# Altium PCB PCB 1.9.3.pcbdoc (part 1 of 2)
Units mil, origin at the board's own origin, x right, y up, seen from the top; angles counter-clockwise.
Board outline 4192.9 x 2374.1 mil, 2 copper layers (Top Layer, Bottom Layer), stack 62.2 mil thick; 67 components, 68 nets, 279 pads, 489 vias.
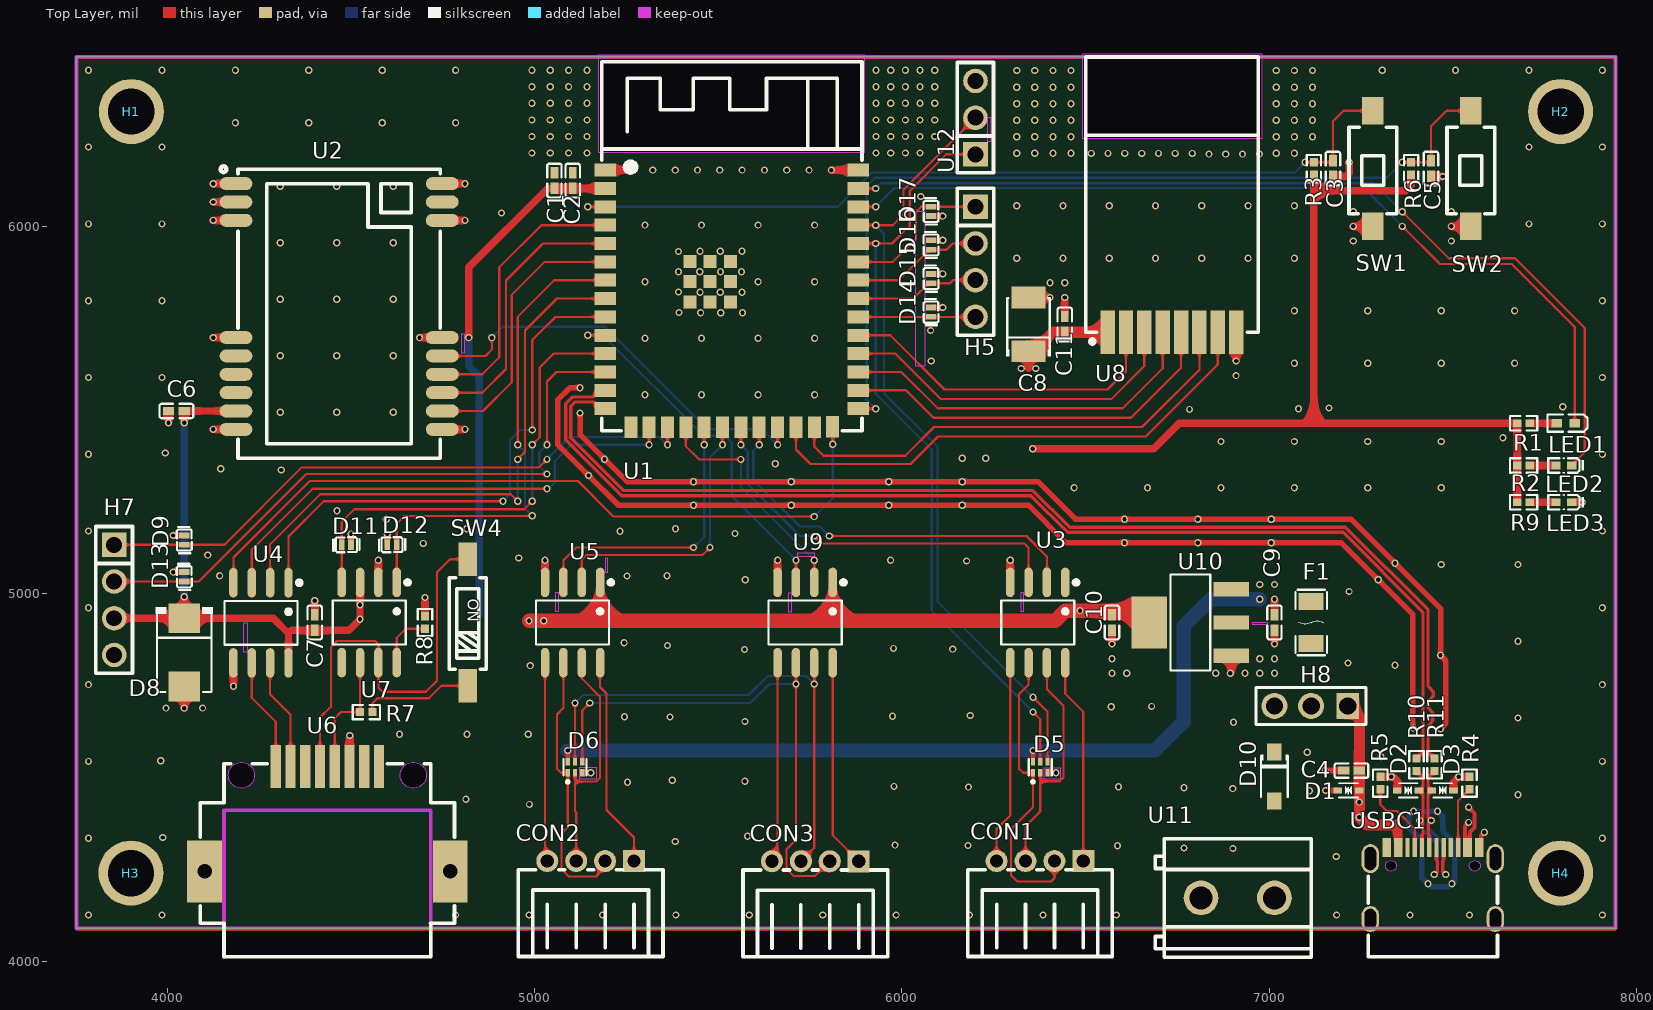
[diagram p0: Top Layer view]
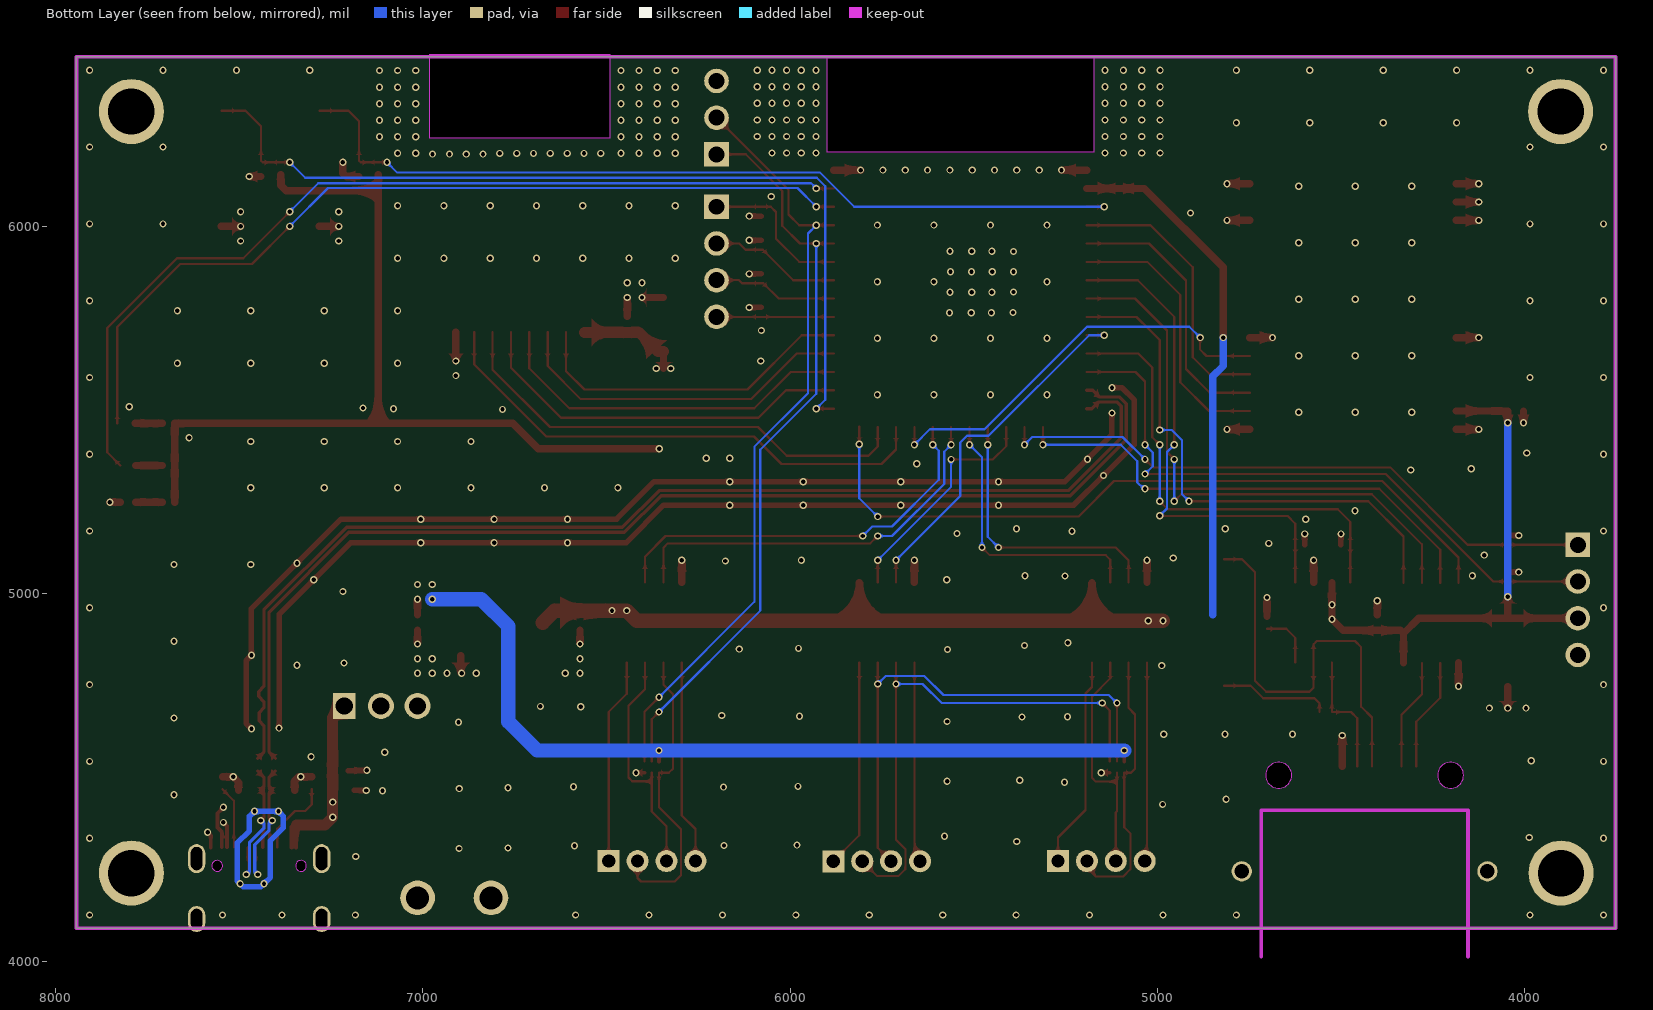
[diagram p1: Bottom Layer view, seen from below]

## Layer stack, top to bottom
Top Solder Mask Layer: solder mask 0.4, Dk 3.3
Top Layer: signal copper 1.4
Dielectric1: surface 59.4, FR4, Dk 4.5
Bottom Layer: signal copper 1.4
Bottom Solder Mask Layer: solder mask 0.4, Dk 3.3

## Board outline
3751.1,6463.8 3751.1,4089.7 7944,4089.7 7944,6463.8
cut-out: 5172.3,6466.8 5172.3,6203.7 5899.1,6203.7 5899.1,6466.8
cut-out: 6491.1,6469.7 6491.1,6240.7 6981.1,6240.7 6981.1,6469.7

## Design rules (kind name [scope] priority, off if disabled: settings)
BoardOutlineClearance copperThickness1oz [All] p0: genericclearance=10 ignorepadtopadclearanceinfootprint=FALSE except(0: Arc-SplitContinuation Track-SplitContinuation SMDPad-SplitContinuation THPad-SplitContinuation Via-SplitContinuation Fill-SplitContinuation Poly-SplitContinuation Region-SplitContinuation Text-SplitContinuation)
BoardOutlineClearance Plane_innerPlane [All] p0: genericclearance=10 ignorepadtopadclearanceinfootprint=FALSE except(0: Arc-SplitContinuation Track-SplitContinuation SMDPad-SplitContinuation THPad-SplitContinuation Via-SplitContinuation Fill-SplitContinuation Poly-SplitContinuation Region-SplitContinuation Text-SplitContinuation)
BoardOutlineClearance Copper_copperRegion [All] p0: genericclearance=10 ignorepadtopadclearanceinfootprint=FALSE except(0: Arc-SplitContinuation Track-SplitContinuation SMDPad-SplitContinuation THPad-SplitContinuation Via-SplitContinuation Fill-SplitContinuation Poly-SplitContinuation Region-SplitContinuation Text-SplitContinuation)
BoardOutlineClearance Copper_CX [All] p0: genericclearance=10 ignorepadtopadclearanceinfootprint=FALSE except(0: Arc-SplitContinuation Track-SplitContinuation SMDPad-SplitContinuation THPad-SplitContinuation Via-SplitContinuation Fill-SplitContinuation Poly-SplitContinuation Region-SplitContinuation Text-SplitContinuation)
BoardOutlineClearance otherClearance [All] p0: genericclearance=10 ignorepadtopadclearanceinfootprint=FALSE except(0: Arc-SplitContinuation Track-SplitContinuation SMDPad-SplitContinuation THPad-SplitContinuation Via-SplitContinuation Fill-SplitContinuation Poly-SplitContinuation Region-SplitContinuation Text-SplitContinuation)
Clearance copperThickness1oz [All] p1: gap=7 ignorepadtopadclearanceinfootprint=FALSE
Clearance Plane_innerPlane [All] p1: gap=7 ignorepadtopadclearanceinfootprint=FALSE
Clearance Copper_copperRegion [All] p1: gap=7 ignorepadtopadclearanceinfootprint=FALSE
Clearance Copper_CX [All] p1: gap=7 ignorepadtopadclearanceinfootprint=FALSE
Clearance otherClearance [All] p1: gap=7 ignorepadtopadclearanceinfootprint=FALSE
DiffPairsRouting differentialPair [All] p1: maxuncoupledlength=10 minlimit=5 maxlimit=Infinity mostfreqgap=5 toplayer_minwidth=9 toplayer_prefwidth=9 toplayer_maxwidth=9 bottomlayer_minwidth=9 bottomlayer_prefwidth=9 bottomlayer_maxwidth=9
PasteMaskExpansion pasteMaskExpansion [All] p1: expansion=0
PlaneConnect innerPlane [All] p1: planeconnectstyle=Relief reliefexpansion=20 reliefentries=4 reliefconductorwidth=10 reliefairgap=10
PolygonConnect copperRegion [All] p1: connectstyle=Direct reliefentries=4 reliefconductorwidth=10 polygonreliefangle="90 Angle" airgapwidth=10
PolygonConnect CX [All] p1: connectstyle=Direct reliefentries=4 reliefconductorwidth=10 polygonreliefangle="90 Angle" airgapwidth=10
RoutingVias viaSize [All] p1: viastyle="Through Hole" holewidth=11.8 minholewidth=11.8 maxholewidth=11.8 width=11.8 minwidth=11.8 maxwidth=11.8
SolderMaskExpansion solderMaskExpansion [IsVia] p1: useseparateexpansions=TRUE expansion=-1000 expansionbottom=-1000
SolderMaskExpansion solderMaskExpansion [All] p2: useseparateexpansions=TRUE expansion=2 expansionbottom=2
Width copperThickness1oz [All] p1: maxlimit=100 minlimit=5 preferedwidth=6

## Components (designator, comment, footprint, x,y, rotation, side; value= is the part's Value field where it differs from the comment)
C1 "22uF" C0402_4#1 5053.2,6126.1 r270 top
C2 "100nF" C0402_4#1 5103.2,6126.1 r270 top
C3 "100nF" C0402_4#1 7174.1,6158.8 r90 top
C4 "100nF" C0402_4#1 7224.5,4518.7 r0 top
C5 "100nF" C0402_4#1 7441.1,6158.8 r90 top
C6 "100nF" C0402_4#1 4023.4,5498.3 r0 top
C7 "100nF" C0402_4#2 4400.1,4922.1 r270 top
C8 "100uF" CASE-B_3531 6344.7,5734.2 r90 top
C9 "10uF" C0402_4#2 7014.7,4922.1 r270 top
C10 "10uF" C0402_4#3 6572.1,4922.1 r90 top
C11 "100nF" C0402_4#3 6443.3,5734.2 r90 top
CON1 "PH-4AW_C722777" CONN-TH_PH-4AW_C722777_3 6376,4272.2 r0 top
CON2 "PH-4AW_C722777" CONN-TH_PH-4AW_C722777_3 5152,4272.2 r0 top
CON3 "PH-4AW_C722777" CONN-TH_PH-4AW_C722777_3 5764,4271.7 r0 top
D1 "LESD5D5.0CT1G" SOD-523_L1.2-W0.8-LS1.6-BI_4#1 7216.4,4464.7 r0 top
D2 "LESD5D5.0CT1G" SOD-523_L1.2-W0.8-LS1.6-BI_4#2 7379.2,4464.7 r0 top
D3 "LESD5D5.0CT1G" SOD-523_L1.2-W0.8-LS1.6-BI_4#1 7473.2,4464.7 r180 top
D5 "TPD4E004DRYR" SON-6_L1.5-W1.0-P0.50-BL_4#1 6376.7,4528 r0 top
D6 "TPD4E004DRYR" SON-6_L1.5-W1.0-P0.50-BL_4#2 5109.4,4528 r0 top
D8 "SMLVT3V3" SMB_L4.6-W3.6-LS5.3-RD_3 4044.9,4840.9 r270 top
D9 "DESD3V3E1BL-7B" X1-DFN1006-2_L1.0-W0.6-P0.65-BI_2 4044.9,5146.6 r270 top
D10 "LMBR220FT1G" SOD-123F_L2.7-W1.7-LS3.7-RD-1_5 7014.7,4502.7 r270 top
D11 "DESD3V3E1BL-7B" X1-DFN1006-2_L1.0-W0.6-P0.65-BI_2 4486.5,5133.8 r0 top
D12 "DESD3V3E1BL-7B" X1-DFN1006-2_L1.0-W0.6-P0.65-BI_2 4610.9,5133.8 r180 top
D13 "DESD3V3E1BL-7B" X1-DFN1006-2_L1.0-W0.6-P0.65-BI_2 4044.9,5046.6 r270 top
D14 "DESD3V3E1BL-7B" X1-DFN1006-2_L1.0-W0.6-P0.65-BI_2 6079.1,5767.6 r270 top
D15 "DESD3V3E1BL-7B" X1-DFN1006-2_L1.0-W0.6-P0.65-BI_2 6079.1,5859.1 r270 top
D16 "DESD3V3E1BL-7B" X1-DFN1006-2_L1.0-W0.6-P0.65-BI_2 6079.1,5950.6 r270 top
D17 "DESD3V3E1BL-7B" X1-DFN1006-2_L1.0-W0.6-P0.65-BI_2 6079.1,6042 r90 top
F1 "Resettable Fuse" F1206_3 7114.7,4922.1 r90 top
H1 "PZ254V-11-01P" HDR-TH_1P-P2.54-V-M_2 3900.7,6314.2 r0 top
H2 "PZ254V-11-01P" HDR-TH_1P-P2.54-V-M_2 7794.4,6314.2 r0 top
H3 "PZ254V-11-01P" HDR-TH_1P-P2.54-V-M_2 3899.7,4239.4 r0 top
H4 "PZ254V-11-01P" HDR-TH_1P-P2.54-V-M_2 7794.4,4239.4 r0 top
H5 "Header-Male-2.54_1x4" HDR-TH_4P-P2.54-V-M_3 6200.3,5904.8 r270 top
H7 "Header-Male-2.54_1x4" HDR-TH_4P-P2.54-V-M_3 3853.9,4983.8 r270 top
H8 "Header-Male-2.54_1x3" HDR-TH_3P-P2.54-V-M-1_3 7114.7,4694.9 r180 top
LED1 "BLUE" LED0402-R-RD_3 7808.2,5464.9 r180 top
LED2 "GREEN" LED0402-RD_GREEN_3 7803.2,5349.9 r180 top
LED3 "White" LED0402-RD_WHITE_3 7803.2,5249.9 r180 top
R1 "1.5kΩ" R0402_3#1 7693.2,5464.9 r0 top
R2 "1.5kΩ" R0402_3#1 7693.2,5349.9 r0 top
R3 "10kΩ" R0402_3#2 7122.1,6158.8 r270 top
R4 "5.1kΩ" R0402_3#3 7546.2,4484.7 r270 top
R5 "5.1kΩ" R0402_3#3 7303.2,4484.7 r270 top
R6 "10kΩ" R0402_3#2 7387.1,6158.8 r270 top
R7 "120Ω" R0402_3#2 4540.8,4678.2 r180 top
R8 "10kΩ" R0402_3#3 4700.8,4922.1 r270 top
R9 "1.5kΩ" R0402_3#3 7693.2,5249.9 r180 top
R10 "22Ω" R0402_3#1 7401.7,4534.7 r90 top
R11 "22Ω" R0402_3#1 7450.6,4534.7 r90 top
SW1 "TS-1101-C-W" SW-SMD_L6.0-W3.3-LS8.0_3 7282.1,6158.8 r90 top
SW2 "TS-1101-C-W" SW-SMD_L6.0-W3.3-LS8.0_3 7549.1,6158.8 r90 top
SW4 "DSIC01LSGET" SW-SMD_DSIC01LSGET_3 4817.1,4922.1 r0 top
U1 "ESP32-S3-WROOM-1-N16R8" WIRELM-SMD_ESP32-S3-WROOM-1_4 5536.2,5804.4 r0 top
U2 "E49-900M20S" WIRELM-SMD_E49-400M20S_3 4466.8,5783 r180 top
U3 "ADUM1201AR-RL7" SOIC-8_L4.9-W3.9-P1.27-LS6.0-BL_3 6369.8,4922.1 r180 top
U4 "ISL3178EIBZ-T" SOIC-8_L4.9-W3.9-P1.27-LS6.0-BL_3 4253.8,4921.2 r180 top
U5 "ADUM1201AR-RL7" SOIC-8_L4.9-W3.9-P1.27-LS6.0-BL_3 5102.6,4922.1 r180 top
U6 "HC-RJ45-055-4" RJ45-SMD_HC-RJ45-055-4_5 4434.7,4387 r0 top
U7 "SN65HVD230DR" SOIC-8_L4.9-W3.9-P1.27-LS6.0-BL_3 4548.7,4922.1 r180 top
U8 "E01-ML01S" WIRELM-SMD_E01-ML01S_3 6735.3,5712.8 r0 top
U9 "ADUM1201AR-RL7" SOIC-8_L4.9-W3.9-P1.27-LS6.0-BL_3 5736.2,4922.1 r180 top
U10 "AMS1117-3.3" SOT-223-4_L6.5-W3.5-P2.30-LS7.0-BR_3 6785.6,4922.1 r0 top
U11 "KF127-5.08-2P" CONN-TH_P5.08_KF127-5.08-2P_3 6914.7,4172 r0 top
U12 "HB-PH3-25413PB2GOP" HDR-TH_3P-P2.54-V-M_3 6200.3,6297.5 r90 top
USBC1 "TYPE-C-31-M-12" USB-C_SMD-TYPE-C-31-M-12_3 7446.2,4211.8 r0 top

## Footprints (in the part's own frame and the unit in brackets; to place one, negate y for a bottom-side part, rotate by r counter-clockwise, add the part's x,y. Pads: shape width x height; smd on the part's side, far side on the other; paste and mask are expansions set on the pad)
C0402_4#1 [mil]
  rect 31.1x21.3 smd paste-3937 mask+2: 1(-21.5,0) 2(21.5,0)
  silkscreen extent -46,-20 46,20
C0402_4#2 [mil]
  rect 31.1x21.3 smd paste-3937 mask+2: 1(-21.5,0) 2(21.4,0)
  silkscreen extent -46,-20 46,20
C0402_4#3 [mil]
  rect 31.1x21.3 smd paste-3937 mask+2: 1(-21.4,0) 2(21.5,0)
  silkscreen extent -46,-20 46,20
CASE-B_3531 [mil]
  rect 59.3x93.5 smd: 1(-73.2,0) 2(73.3,0)
  silkscreen extent -87,-61 72,61
CONN-TH_P5.08_KF127-5.08-2P_3 [mil]
  round 94.5 hole 63: 1(-100,0) 2(100,0)
  silkscreen extent -225,-161 200,161
CONN-TH_PH-4AW_C722777_3 [mil]
  rect 60x60 hole 36: 1(118.1,0)
  round 60 hole 36: 2(39.3,0) 3(-39.4,0) 4(-118.2,0)
  silkscreen extent -197,-260 197,-24
F1206_3 [mil]
  rect 46.9x68 smd: 1(-56.8,0) 2(56.9,0)
  silkscreen extent -89,-43 89,43
HDR-TH_1P-P2.54-V-M_2 [mil]
  round 177.2 hole 126: 1(0,0)
HDR-TH_3P-P2.54-V-M-1_3 [mil]
  rect 62x70.9 hole 47.2: 1(-100,0)
  round 70.9 hole 47.2: 2(0,0) 3(100,0)
  silkscreen extent -150,-50 150,50
HDR-TH_3P-P2.54-V-M_3 [mil]
  rect 66.9x66.9 hole 43.3: 1(-100,0)
  round 66.9 hole 43.3: 2(0,0) 3(100,0)
  silkscreen extent -150,-49 150,49
HDR-TH_4P-P2.54-V-M_3 [mil]
  rect 66.9x66.9 hole 43.3: 1(-150,0)
  round 66.9 hole 43.3: 2(-50,0) 3(50,0) 4(150,0)
  silkscreen extent -200,-50 200,50
LED0402-R-RD_3 [mil]
  rect 29.5x23.6 smd: 1(24.5,0) 2(-24.5,0)
  silkscreen extent -60,-24 50,23
LED0402-RD_GREEN_3 [mil]
  rect 25.1x21.3 smd paste-3937 mask+2: 1(-21.2,0) 2(21.2,0)
  silkscreen extent -55,-21 43,21
LED0402-RD_WHITE_3 [mil]
  rect 25.1x21.3 smd paste-3937 mask+2: 1(-21.2,0) 2(21.2,0)
  silkscreen extent -55,-21 43,21
R0402_3#1 [mil]
  rect 22.3x21.3 smd paste-3937 mask+2: 1(-17,0) 2(17.1,0)
  silkscreen extent -37,-20 37,20
R0402_3#2 [mil]
  rect 22.3x21.3 smd paste-3937 mask+2: 1(-17,0) 2(17,0)
  silkscreen extent -37,-20 37,20
R0402_3#3 [mil]
  rect 22.3x21.3 smd paste-3937 mask+2: 1(-17.1,0) 2(17,0)
  silkscreen extent -37,-20 37,20
RJ45-SMD_HC-RJ45-055-4_5 [mil]
  rect 27.6x118.1 smd paste-3937 mask+2: 1(-140.5,142.7) 2(-100.4,142.7) 3(-60.2,142.7) 4(-20.1,142.7) 5(20.1,142.7) 6(60.2,142.7) 7(100.4,142.7) 8(140.6,142.7)
  rect 94.5x169.3 smd paste-3937 mask+2: 9(-334.6,-142.7) 10(334.7,-142.7)
  round 55.1 hole 39.4 paste+0 mask+2: 9(-334.6,-142.7) 10(334.7,-142.7)
  Board Outline Layer lines w0.1: -269.7,119.1 -269.3,113.8 -268.1,108.6 -266.2,103.7 -263.5,99.1 -260.2,95 -256.3,91.4 -252,88.4 -247.2,86.1 -242.1,84.5 -236.9,83.8 -231.6,83.8 -226.4,84.5 -221.3,86.1 -216.5,88.4 -212.1,91.4 -208.3,95 -205,99.1 -202.3,103.7 -200.4,108.6 -199.2,113.8 -198.8,119.1 -199.2,124.4 -200.4,129.5 -202.3,134.5 -205,139 -208.3,143.2 -212.1,146.8 -216.5,149.8 -221.3,152.1 -226.4,153.6 -231.6,154.4 -236.9,154.4 -242.1,153.6 -247.2,152.1 -252,149.8 -256.3,146.8 -260.2,143.2 -263.5,139 -266.2,134.5 -268.1,129.5 -269.3,124.4 -269.7,119.1 ; 198.8,119.1 199.2,113.8 200.4,108.6 202.3,103.7 205,99.1 208.3,95 212.2,91.4 216.5,88.4 221.3,86.1 226.4,84.5 231.6,83.8 236.9,83.8 242.1,84.5 247.2,86.1 252,88.4 256.4,91.4 260.2,95 263.5,99.1 266.2,103.7 268.1,108.6 269.3,113.8 269.7,119.1 269.3,124.4 268.1,129.5 266.2,134.5 263.5,139 260.2,143.2 256.4,146.8 252,149.8 247.2,152.1 242.1,153.6 236.9,154.4 231.6,154.4 226.4,153.6 221.3,152.1 216.5,149.8 212.2,146.8 208.3,143.2 205,139 202.3,134.5 200.4,129.5 199.2,124.4 198.8,119.1
  Board Outline Layer lines w10: -281.5,-375 -281.5,23.6 281.5,23.6 ; 281.5,-375 281.5,23.6 ; 281.5,23.6 281.5,23.6
  Board Outline Layer region: -198.8,119.1 -199.2,113.8 -200.4,108.6 -202.3,103.7 -205,99.1 -208.3,95 -212.1,91.4 -216.5,88.4 -221.3,86.1 -226.4,84.5 -231.6,83.8 -236.9,83.8 -242.1,84.5 -247.2,86.1 -252,88.4 -256.3,91.4 -260.2,95 -263.5,99.1 -266.2,103.7 -268.1,108.6 -269.3,113.8 -269.7,119.1 -269.3,124.4 -268.1,129.5 -266.2,134.5 -263.5,139 -260.2,143.2 -256.3,146.8 -252,149.8 -247.2,152.1 -242.1,153.6 -236.9,154.4 -231.6,154.4 -226.4,153.6 -221.3,152.1 -216.5,149.8 -212.1,146.8 -208.3,143.2 -205,139 -202.3,134.5 -200.4,129.5 -199.2,124.4
  Board Outline Layer region: -198.8,119.1 -199.2,113.8 -200.4,108.6 -202.3,103.7 -205,99.1 -208.3,95 -212.1,91.4 -216.5,88.4 -221.3,86.1 -226.4,84.5 -231.6,83.8 -236.9,83.8 -242.1,84.5 -247.2,86.1 -252,88.4 -256.3,91.4 -260.2,95 -263.5,99.1 -266.2,103.7 -268.1,108.6 -269.3,113.8 -269.7,119.1 -269.3,124.4 -268.1,129.5 -266.2,134.5 -263.5,139 -260.2,143.2 -256.3,146.8 -252,149.8 -247.2,152.1 -242.1,153.6 -236.9,154.4 -231.6,154.4 -226.4,153.6 -221.3,152.1 -216.5,149.8 -212.1,146.8 -208.3,143.2 -205,139 -202.3,134.5 -200.4,129.5 -199.2,124.4
  Board Outline Layer region: 269.7,119.1 269.3,113.8 268.1,108.6 266.2,103.7 263.5,99.1 260.2,95 256.4,91.4 252,88.4 247.2,86.1 242.1,84.5 236.9,83.8 231.6,83.8 226.4,84.5 221.3,86.1 216.5,88.4 212.2,91.4 208.3,95 205,99.1 202.3,103.7 200.4,108.6 199.2,113.8 198.8,119.1 199.2,124.4 200.4,129.5 202.3,134.5 205,139 208.3,143.2 212.2,146.8 216.5,149.8 221.3,152.1 226.4,153.6 231.6,154.4 236.9,154.4 242.1,153.6 247.2,152.1 252,149.8 256.4,146.8 260.2,143.2 263.5,139 266.2,134.5 268.1,129.5 269.3,124.4
  Board Outline Layer region: 269.7,119.1 269.3,113.8 268.1,108.6 266.2,103.7 263.5,99.1 260.2,95 256.4,91.4 252,88.4 247.2,86.1 242.1,84.5 236.9,83.8 231.6,83.8 226.4,84.5 221.3,86.1 216.5,88.4 212.2,91.4 208.3,95 205,99.1 202.3,103.7 200.4,108.6 199.2,113.8 198.8,119.1 199.2,124.4 200.4,129.5 202.3,134.5 205,139 208.3,143.2 212.2,146.8 216.5,149.8 221.3,152.1 226.4,153.6 231.6,154.4 236.9,154.4 242.1,153.6 247.2,152.1 252,149.8 256.4,146.8 260.2,143.2 263.5,139 266.2,134.5 268.1,129.5 269.3,124.4
  Multi-Layer board cut-out: -198.8,119.1 -199.2,113.8 -200.4,108.6 -202.3,103.7 -205,99.1 -208.3,95 -212.1,91.4 -216.5,88.4 -221.3,86.1 -226.4,84.5 -231.6,83.8 -236.9,83.8 -242.1,84.5 -247.2,86.1 -252,88.4 -256.3,91.4 -260.2,95 -263.5,99.1 -266.2,103.7 -268.1,108.6 -269.3,113.8 -269.7,119.1 -269.3,124.4 -268.1,129.5 -266.2,134.5 -263.5,139 -260.2,143.2 -256.3,146.8 -252,149.8 -247.2,152.1 -242.1,153.6 -236.9,154.4 -231.6,154.4 -226.4,153.6 -221.3,152.1 -216.5,149.8 -212.1,146.8 -208.3,143.2 -205,139 -202.3,134.5 -200.4,129.5 -199.2,124.4
  Multi-Layer board cut-out: 269.7,119.1 269.3,113.8 268.1,108.6 266.2,103.7 263.5,99.1 260.2,95 256.4,91.4 252,88.4 247.2,86.1 242.1,84.5 236.9,83.8 231.6,83.8 226.4,84.5 221.3,86.1 216.5,88.4 212.2,91.4 208.3,95 205,99.1 202.3,103.7 200.4,108.6 199.2,113.8 198.8,119.1 199.2,124.4 200.4,129.5 202.3,134.5 205,139 208.3,143.2 212.2,146.8 216.5,149.8 221.3,152.1 226.4,153.6 231.6,154.4 236.9,154.4 242.1,153.6 247.2,152.1 252,149.8 256.4,146.8 260.2,143.2 263.5,139 266.2,134.5 268.1,129.5 269.3,124.4
  silkscreen extent -346,-375 346,151
SMB_L4.6-W3.6-LS5.3-RD_3 [mil]
  rect 80.6x86.3 smd: 1(-92.9,0) 2(93,0)
  silkscreen extent -123,-77 108,77
SOD-123F_L2.7-W1.7-LS3.7-RD-1_5 [mil]
  rect 47.2x39.4 smd: 1(-66.9,0) 2(67,0)
  silkscreen extent -59,-37 56,37
SOD-523_L1.2-W0.8-LS1.6-BI_4#1 [mil]
  rect 23.6x15.7 smd: 1(-29.5,0) 2(29.6,0)
  silkscreen extent -26,-20 26,20
SOD-523_L1.2-W0.8-LS1.6-BI_4#2 [mil]
  rect 23.6x15.7 smd: 1(-29.6,0) 2(29.5,0)
  silkscreen extent -26,-20 26,20
SOIC-8_L4.9-W3.9-P1.27-LS6.0-BL_3 [mil]
  oval 23.1x80.5 smd: 1(-75,-109.2) 2(-25,-109.2) 3(25,-109.2) 4(75,-109.2) 5(75,109.1) 6(25,109.1) 7(-25,109.1) 8(-75,109.1)
  silkscreen extent -110,-115 99,60
SON-6_L1.5-W1.0-P0.50-BL_4#1 [mil]
  rect 11.8x20.5 smd: 1(-19.7,-15.1) 2(0,-15.1) 3(19.7,-15.1) 4(19.7,15.2) 5(0,15.2) 6(-19.7,15.2)
  silkscreen extent -32,-44 32,23
SON-6_L1.5-W1.0-P0.50-BL_4#2 [mil]
  rect 11.8x20.5 smd: 1(-19.6,-15.1) 2(0,-15.1) 3(19.7,-15.1) 4(19.7,15.2) 5(0,15.2) 6(-19.6,15.2)
  silkscreen extent -32,-44 32,23
SOT-223-4_L6.5-W3.5-P2.30-LS7.0-BR_3 [mil]
  rect 97.2x38.6 smd: 1(111.6,-90.5) 2(111.6,0) 3(111.6,90.6)
  rect 97.2x141.7 smd: 4(-111.6,0)
  silkscreen extent -54,-131 54,131
SW-SMD_DSIC01LSGET_3 [mil]
  rect 51.2x90.6 smd: 1(0,172.3) 2(0,-172.2)
  silkscreen extent -50,-128 50,122
SW-SMD_L6.0-W3.3-LS8.0_3 [mil]
  rect 74.8x59.1 smd: 1(-157.5,0) 2(157.5,0)
  silkscreen extent -124,-66 113,64
USB-C_SMD-TYPE-C-31-M-12_3 [mil]
  oval 47.2x78.7 hole 31.5 slot 63 at 90 deg: 0(-170.3,67.2) 1(170.3,67.2)
  oval 47.2x70.9 hole 31.5 slot 55.1 at 90 deg: 2(170.3,-97.4) 3(-170.3,-97.4)
  rect 11.8x51.2 smd paste-3937 mask+2: A1(-131.9,97.4) A4(-100.4,97.4) A5(-49.2,97.4) A6(-9.9,97.4) A7(9.8,97.4) A8(49.2,97.4) A9(100.4,97.4) A12(131.9,97.4) B1(120.1,97.4) B4(88.6,97.4) B5(68.9,97.4) B6(29.5,97.4) B7(-29.6,97.4) B8(-68.9,97.4) B9(-88.6,97.4) B12(-120.1,97.4)
  Board Outline Layer lines w0.1: -128.9,45.8 -128.1,42.5 -126.5,39.4 -124.3,36.8 -121.6,34.7 -118.4,33.4 -115.1,32.8 -111.6,33 -108.3,33.9 -105.4,35.7 -102.9,38 -101,40.9 -99.8,44.1 -99.4,47.5 -99.8,50.9 -101,54.1 -102.9,57 -105.4,59.3 -108.3,61.1 -111.6,62 -115.1,62.2 -118.4,61.6 -121.6,60.3 -124.3,58.2 -126.5,55.6 -128.1,52.6 -128.9,49.2 -128.9,45.8 ; 99.5,45.8 100.3,42.5 101.8,39.4 104,36.8 106.8,34.7 109.9,33.4 113.3,32.8 116.7,33 120,33.9 123,35.7 125.5,38 127.3,40.9 128.5,44.1 128.9,47.5 128.5,50.9 127.3,54.1 125.5,57 123,59.3 120,61.1 116.7,62 113.3,62.2 109.9,61.6 106.8,60.3 104,58.2 101.8,55.6 100.3,52.6 99.5,49.2 99.5,45.8
  Board Outline Layer region: -99.4,47.5 -99.8,44.1 -101,40.9 -102.9,38 -105.4,35.7 -108.3,33.9 -111.6,33 -115.1,32.8 -118.4,33.4 -121.6,34.7 -124.3,36.8 -126.5,39.4 -128.1,42.5 -128.9,45.8 -128.9,49.2 -128.1,52.6 -126.5,55.6 -124.3,58.2 -121.6,60.3 -118.4,61.6 -115.1,62.2 -111.6,62 -108.3,61.1 -105.4,59.3 -102.9,57 -101,54.1 -99.8,50.9
  Board Outline Layer region: -99.4,47.5 -99.8,44.1 -101,40.9 -102.9,38 -105.4,35.7 -108.3,33.9 -111.6,33 -115.1,32.8 -118.4,33.4 -121.6,34.7 -124.3,36.8 -126.5,39.4 -128.1,42.5 -128.9,45.8 -128.9,49.2 -128.1,52.6 -126.5,55.6 -124.3,58.2 -121.6,60.3 -118.4,61.6 -115.1,62.2 -111.6,62 -108.3,61.1 -105.4,59.3 -102.9,57 -101,54.1 -99.8,50.9
  Board Outline Layer region: 128.9,47.5 128.5,44.1 127.3,40.9 125.5,38 123,35.7 120,33.9 116.7,33 113.3,32.8 109.9,33.4 106.8,34.7 104,36.8 101.8,39.4 100.3,42.5 99.5,45.8 99.5,49.2 100.3,52.6 101.8,55.6 104,58.2 106.8,60.3 109.9,61.6 113.3,62.2 116.7,62 120,61.1 123,59.3 125.5,57 127.3,54.1 128.5,50.9
  Board Outline Layer region: 128.9,47.5 128.5,44.1 127.3,40.9 125.5,38 123,35.7 120,33.9 116.7,33 113.3,32.8 109.9,33.4 106.8,34.7 104,36.8 101.8,39.4 100.3,42.5 99.5,45.8 99.5,49.2 100.3,52.6 101.8,55.6 104,58.2 106.8,60.3 109.9,61.6 113.3,62.2 116.7,62 120,61.1 123,59.3 125.5,57 127.3,54.1 128.5,50.9
  Multi-Layer board cut-out: -99.4,47.5 -99.8,44.1 -101,40.9 -102.9,38 -105.4,35.7 -108.3,33.9 -111.6,33 -115.1,32.8 -118.4,33.4 -121.6,34.7 -124.3,36.8 -126.5,39.4 -128.1,42.5 -128.9,45.8 -128.9,49.2 -128.1,52.6 -126.5,55.6 -124.3,58.2 -121.6,60.3 -118.4,61.6 -115.1,62.2 -111.6,62 -108.3,61.1 -105.4,59.3 -102.9,57 -101,54.1 -99.8,50.9
  Multi-Layer board cut-out: 128.9,47.5 128.5,44.1 127.3,40.9 125.5,38 123,35.7 120,33.9 116.7,33 113.3,32.8 109.9,33.4 106.8,34.7 104,36.8 101.8,39.4 100.3,42.5 99.5,45.8 99.5,49.2 100.3,52.6 101.8,55.6 104,58.2 106.8,60.3 109.9,61.6 113.3,62.2 116.7,62 120,61.1 123,59.3 125.5,57 127.3,54.1 128.5,50.9
  silkscreen extent -176,-200 176,19
WIRELM-SMD_E01-ML01S_3 [mil]
  rect 39.4x118.1 smd: 1(-175,0) 2(-125,0) 3(-75,0) 4(-25,0) 5(25,0) 6(75,0) 7(125,0) 8(175,0)
  silkscreen extent -235,-31 236,750
WIRELM-SMD_E49-400M20S_3 [mil]
  oval 89.4x35.4 smd paste+0 mask+2: 1(280.9,-334.6) 2(280.9,-284.6) 3(280.9,-234.6) 4(280.9,84.7) 5(280.9,134.7) 6(280.9,184.7) 7(280.9,234.7) 8(280.9,284.7) 9(280.9,334.7) 10(-280.9,334.7) 11(-280.9,284.7) 12(-280.9,234.7) 13(-280.9,184.7) 14(-280.9,134.7) 15(-280.9,84.7) 16(-280.9,-234.6) 17(-280.9,-284.6) 18(-280.9,-334.6)
  silkscreen extent -276,-382 323,413
WIRELM-SMD_ESP32-S3-WROOM-1_4 [mil]
  rect 59.1x35.4 smd paste+0 mask+2: 1(-344.5,350.2) 2(-344.5,300.2) 3(-344.5,250.2) 4(-344.5,200.2) 5(-344.5,150.2) 6(-344.5,100.2) 7(-344.5,50.2) 8(-344.5,0.2) 9(-344.5,-49.8) 10(-344.5,-99.8) 11(-344.5,-149.8) 12(-344.5,-199.8) 13(-344.5,-249.8) 14(-344.5,-299.8) 27(344.5,-299.8) 28(344.5,-249.8) 29(344.5,-199.8) 30(344.5,-149.8) 31(344.5,-99.8) 32(344.5,-49.8) 33(344.5,0.2) 34(344.5,50.2) 35(344.5,100.2) 36(344.5,150.2) 37(344.5,200.2) 38(344.5,250.2) 39(344.5,300.2) 40(344.5,350.2)
  rect 35.4x59.1 smd paste+0 mask+2: 15(-275,-350.1) 16(-225,-350.1) 17(-175,-350.1) 18(-125,-350.1) 19(-75,-350.1) 20(-25,-350.1) 21(25,-350.1) 22(75,-350.1) 23(125,-350.1) 24(175,-350.1) 25(225,-350.1) 26(275,-349)
  rect 35.4x35.4 smd: 41(-114.2,-8.8) 41(-114.2,46.3) 41(-114.2,101.4) 41(-59,-8.8) 41(-59,46.3) 41(-59,101.4) 41(-3.9,-8.8) 41(-3.9,46.3) 41(-3.9,101.4)
  silkscreen extent -354,-360 355,646
X1-DFN1006-2_L1.0-W0.6-P0.65-BI_2 [mil]
  rect 15.7x27.6 smd: 1(-12.8,0) 2(12.8,0)
  silkscreen extent -36,-21 36,20

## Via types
v1: diameter 19.7, hole 11.8, Top Layer to Bottom Layer, 489 vias

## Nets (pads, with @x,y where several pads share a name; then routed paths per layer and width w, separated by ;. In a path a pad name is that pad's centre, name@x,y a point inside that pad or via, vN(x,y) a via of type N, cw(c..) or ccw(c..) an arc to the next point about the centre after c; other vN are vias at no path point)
$1N4: R5.2 USBC1.A5 | length 213.8
  Top Layer w6: R5.2@7303.2,4467.7 7303.2,4426.3 7320.7,4408.7 7348.7,4408.7 7397,4360.5 USBC1.A5@7397,4309.2
$1N5: R4.2 USBC1.B5 | length 171.4
  Top Layer w6: USBC1.B5@7515.1,4309.2 7515.1,4436.6 R4.2@7546.2,4467.7
$1N11: R8.2 U7.8 | length 154.7
  Top Layer w6: U7.8@4623.7,4813 4623.7,4880.3 4648.5,4905.1 R8.2@4700.8,4905.1
$1N13: R7.2 U6.5 U7.6 | length 342.4
  Top Layer w6: U6.5@4454.8,4529.7 4454.8,4661.2 4471.8,4678.2 R7.2@4523.8,4678.2 4523.8,4812.9 U7.6@4523.7,4813
$1N78: U4.6 U6.1 | length 309.5
  Top Layer w6: U4.6@4228.8,4812.1 4228.8,4717.1 4294.2,4651.7 U6.1@4294.2,4529.7
$1N79: U4.7 U6.2 | length 305.4
  Top Layer w6: U4.7@4278.8,4812.1 4278.8,4726.1 4334.3,4670.6 U6.2@4334.3,4529.7
$1N99: SW4.1 U6.4 U7.7 | length 1165.7
  Top Layer w6: U6.4@4414.6,4529.7 4414.6,4663.3 4444.3,4692.9 4444.3,4854.9 4461.1,4871.7 4564.9,4871.7 4573.7,4863 U7.7@4573.7,4813 4573.7,4745.2 4585.1,4733.7 4703.1,4733.7 4733.1,4763.7 4733.1,5058.7 4768.7,5094.4 SW4.1@4817.1,5094.4
$1N106: LED1.1 R1.2 | length 73.4
  Top Layer w20: R1.2@7710.3,5464.9 LED1.1@7783.7,5464.9
$1N110: LED2.2 R2.2 | length 71.7
  Top Layer w20: R2.2@7710.3,5349.9 LED2.2@7782,5349.9
$1N124: CON1.1 U3.8 | length 561.2
  Top Layer w6: U3.8@6444.8,4813 6444.8,4728 6494.1,4678.7 CON1.1@6494.1,4272.2
$1N125: CON1.4 U3.5 | length 556.1
  Top Layer w6: CON1.4@6257.8,4272.2 6257.8,4359.5 6294.8,4396.5 U3.5@6294.8,4813
$1N126: CON2.1 U5.8 | length 579.1
  Top Layer w6: U5.8@5177.6,4813 5177.6,4746.3 5195.1,4728.7 5195.1,4411.5 5270.1,4336.5 CON2.1@5270.1,4272.2
$1N127: CON2.4 U5.5 | length 543.3
  Top Layer w6: U5.5@5027.6,4813 5027.6,4278.5 CON2.4@5033.8,4272.2
$1N128: CON3.1 U9.8 | length 570.6
  Top Layer w6: U9.8@5811.2,4813 5811.2,4342.7 CON3.1@5882.1,4271.7
$1N129: CON3.4 U9.5 | length 547.7
  Top Layer w6: CON3.4@5645.8,4271.7 5661.2,4287.1 U9.5@5661.2,4813
$1N148: F1.1 H8.2
$1N159: R7.1 SW4.2 | length 303.2
  Top Layer w6: R7.1@4557.8,4678.2 4557.8,4702.5 4571.1,4715.7 4711.1,4715.7 4745.3,4749.9 SW4.2@4817.1,4749.9
$1N172: D10.2 U11.2
$1N2071: LED3.2 R9.1 | length 71.7
  Top Layer w20: R9.1@7710.3,5249.9 LED3.2@7782,5249.9
+3V3: C1.2 C2.2 C6.2 C7.2 C8.1 C10.2 C11.1 D8.1 H7.3 R1.1 R2.1 R3.2 R6.2 R9.2 U1.2 U2.8 U3.1 U4.8 U5.1 U7.3 U8.1 U9.1 U10.2 U10.4 | length 7756.6
  Top Layer w20: H7.3@3853.9,4933.8 D8.1@4044.9,4933.8 ; v1(4044.9,4992.5) D8.1@4044.9,4933.8 ; v1(4044.9,5466.3) C6.2@4044.9,5498.3 U2.8@4185.9,5498.3 ; U4.8@4328.8,4812.1 4328.8,4892 ; U7.3@4523.7,5031.3 v1(4523.7,4970.8) v1(4523.7,4930.8) 4493.5,4900.7 C7.2@4400.1,4900.7 4337.4,4900.7 4328.8,4892 ; v1(4819.8,5698.3) 4819.8,5889.5 5035,6104.6 C1.2@5053.2,6104.6 C2.2@5103.2,6104.6 U1.2@5191.7,6104.6 ; 5177.6,4926.7 U5.1@5177.6,5031.3 ; 5811.2,4926.7 U9.1@5811.2,5031.3 ; 6344.7,5614.1 C8.1@6344.7,5661 ; v1(6356.1,5395.7) 6686.1,5395.7 6755.3,5464.9 7122.1,5464.9 ; R3.2@7122.1,6141.8 7122.1,6098.7 ; R6.2@7387.1,6141.8 7387.1,6113.7 7372.1,6098.7 7122.1,6098.7 ; R9.2@7676.2,5249.9 R2.1@7676.2,5349.9 R1.1@7676.2,5464.9 7122.1,5464.9 ; D8.1@4044.9,4933.8 4287,4933.8 4328.8,4892 ; 7122.1,5464.9 7122.1,6098.7
  Top Layer w30: C8.1@6344.7,5661 6359.3,5661 6411.1,5712.8 C11.1@6443.3,5712.8 U8.1@6560.3,5712.8
  Top Layer w39.4: v1(4984.1,4926.7) v1(5024.1,4926.7) 5177.6,4926.7 5811.2,4926.7 6417.1,4926.7 v1(6444.8,4954.5) v1(6484.8,4954.5) 6641.6,4954.5 U10.4@6674,4922.1
  Bottom Layer w20: v1(4044.9,4992.5) v1(4044.9,5466.3) ; v1(4819.8,5698.3) 4819.8,5621 4848.1,5592.7 4848.1,4942.7
  other v1: 6324.7,5614.1 6364.7,5614.1
+5V: C9.1 D5.6 D6.6 F1.2 U10.3 | length 2310.6
  Top Layer w10: D6.6@5089.8,4543.2 v1(5089.8,4573.5) ; D5.6@6357,4543.2 v1(6357,4573.5)
  Top Layer w20: C9.1@7014.7,4943.6 v1(7014.7,4985.7)
  Bottom Layer w39.4: v1(5089.8,4573.5) v1(6357,4573.5) 6688.9,4573.5 6767.1,4651.7 6767.1,4911.7 6841.1,4985.7 v1(6974.7,4985.7)
  other v1: 6974.7,5025.7 7014.7,5025.7
CMT_CLK: U1.6 U2.11 | length 751.7
  Top Layer w6: U2.11@4747.7,5498.3 4858.7,5498.3 4937.1,5576.7 4937.1,5814.7 5027,5904.6 U1.6@5191.7,5904.6
CMT_CS: U1.4 U2.13 | length 755.8
  Top Layer w6: U2.13@4747.7,5598.3 4856.7,5598.3 4903.1,5644.7 4903.1,5889.7 5018,6004.6 U1.4@5191.7,6004.6
CMT_FCS: U1.23 U2.14 | length 1146.4
  Top Layer w6: U2.14@4747.7,5648.3 4865.7,5648.3 4882.8,5665.5 v1(4882.8,5698.3) ; v1(5661.2,5406.5) U1.23@5661.2,5454.3
  Bottom Layer w6: v1(4882.8,5698.3) 4912.3,5727.7 5191.1,5727.7 5470.1,5448.7 5619,5448.7 v1(5661.2,5406.5)
CMT_SDIO: U1.5 U2.12 | length 753.5
  Top Layer w6: U2.12@4747.7,5548.3 4856.7,5548.3 4921.1,5612.7 4921.1,5853.7 5022,5954.6 U1.5@5191.7,5954.6
D+: R11.2 U1.14 | length 3155.3
  Top Layer w9: U1.14@5191.7,5504.6 5177.5,5504.6 5159.5,5522.6 5108.8,5522.6 5098.1,5511.9 5098.1,5425.7 5242.1,5281.7 6356.9,5281.7 6456.9,5181.7 7207.9,5181.7 7433.2,4956.5 7433.2,4748.3 7447.7,4733.7 7447.7,4720.7 7433.2,4706.2 7433.2,4689.3 7445.8,4676.6 7445.8,4653.9 7433.2,4641.2 7433.2,4569.3 R11.2@7450.6,4551.8
D-: R10.2 U1.13 | length 3156.3
  Top Layer w9: U1.13@5191.7,5554.6 5175,5554.6 5157,5536.6 5103,5536.6 5084.1,5517.7 5084.1,5419.9 5236.3,5267.7 6351.1,5267.7 6451.1,5167.7 7202.1,5167.7 7419.2,4950.7 7419.2,4569.3 R10.2@7401.7,4551.8
DE: U1.16 U4.3 | length 1367.2
  Top Layer w6: U4.3@4228.8,5030.4 4228.8,5120.4 4394.9,5286.5 v1(5033.1,5286.5) ; v1(5311.2,5406.5) U1.16@5311.2,5454.3
  Bottom Layer w6: v1@5038.1,5287.7 5054.1,5303.7 5054.1,5361.7 5098.9,5406.5 v1(5311.2,5406.5)
DI: U1.26 U4.4 | length 2043.4
  Top Layer w6: U4.4@4178.8,5030.4 4178.8,5099.4 4387,5307.7 5117.2,5307.7 5214.2,5210.6 v1(5761.2,5210.6) ; v1(5811.2,5407.7) U1.26@5811.2,5455.4
  Bottom Layer w6: v1(5761.2,5210.6) 5811.2,5260.7 v1(5811.2,5407.7)
DN: D2.2 R10.1 USBC1.A7 USBC1.B7 | length 481.6
  Top Layer w9: R10.1@7401.7,4517.7 7419.2,4500.2 7419.2,4475.2 D2.2@7408.7,4464.7 7419.2,4454.2 7419.2,4391.2 v1(7410.7,4382.7) 7419.5,4374 7419.5,4346.7 7416.6,4343.8 USBC1.B7@7416.6,4309.2 ; v1(7450.1,4235.7) 7458.9,4244.5 7458.9,4271.8 7456,4274.7 USBC1.A7@7456,4309.2
  Bottom Layer w9: v1(7410.7,4382.7) 7419.2,4374.2 7419.2,4356.2 7458.6,4316.9 7458.6,4244.2 v1(7450.1,4235.7)
DP: D3.2 R11.1 USBC1.A6 USBC1.B6 | length 480.7
  Top Layer w9: USBC1.A6@7436.3,4309.2 7436.3,4343.8 7433.5,4346.7 7433.5,4374.5 v1(7441.7,4382.7) 7433.2,4391.2 7433.2,4454.3 D3.2@7443.6,4464.7 7433.2,4475.2 7433.2,4500.2 R11.1@7450.6,4517.7 ; USBC1.B6@7475.7,4309.2 7475.7,4274.7 7472.9,4271.8 7472.9,4244 v1(7481.1,4235.7)
  Bottom Layer w9: v1(7441.7,4382.7) 7433.2,4374.2 7433.2,4362 7472.6,4322.7 7472.6,4244.2 v1(7481.1,4235.7)
EN: C3.2 R3.1 SW1.2 U1.3 | length 2357.2
  Top Layer w6: v1(5144,6054.6) U1.3@5191.7,6054.6 ; v1(7098.1,6175.8) R3.1@7122.1,6175.8 7169.7,6175.8 C3.2@7174.1,6180.3 7174.1,6287.7 7202.6,6316.3 SW1.2@7282.1,6316.3
  Bottom Layer w6: v1(5144,6054.6) 5825,6054.6 5918.1,6147.7 7070,6147.7 v1(7098.1,6175.8)
EXT_5V: D10.1 H8.3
